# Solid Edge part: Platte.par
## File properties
Sűrűség: 0,000 kg/m^3
Pontosság: 0,990
Author: bmolnar
Last saved by: bmolnar
Revision: 77
Username: bmolnar
Dokumentum tartalom típus: 0
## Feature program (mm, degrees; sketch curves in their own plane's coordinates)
base feature "unnamed BaseFeature 1"
thread "unnamed Thread 1"
thread "unnamed Thread 2"
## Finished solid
Body 1: solid body, 65 faces, 114 edges, 88 vertices.
  Faces by surface: plane 38, cylinder 12, cone 10, torus 5
  Edges by curve: line 60, circle 36, spline 18
Bounding box of the edges (mm; curved faces can reach further): 105.000 x 30.000 x 12.000, from (-52.5, -15, -6) to (52.5, 15, 6).
Cylindrical faces by radius (mm): R2.4585 x2, R2.5 x2, R2.9 x2, R4.25 x2, R5 x2, R6.5 x1, R11 x1
Conical faces (half-angle, radius in mm at the cone's reference point): 45 deg R2.9585 x4, 45 deg R3 x2, 45 deg R11.25 x1, 60 deg R1 x2, 60 deg R1.4434 x1
Toroidal faces (ring radius, tube radius in mm): R2.6 r0.1 x2, R3.75 r0.5 x2, R5.7 r0.8 x1
Planar faces by outward normal: +x 1, +y 4, +z 7, -x 1, -y 4, -z 5, oblique 16
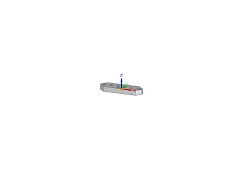
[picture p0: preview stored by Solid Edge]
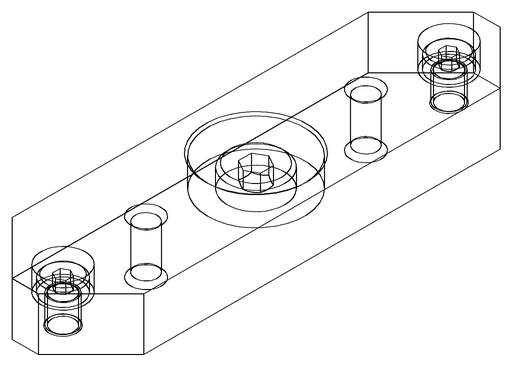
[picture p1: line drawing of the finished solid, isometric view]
